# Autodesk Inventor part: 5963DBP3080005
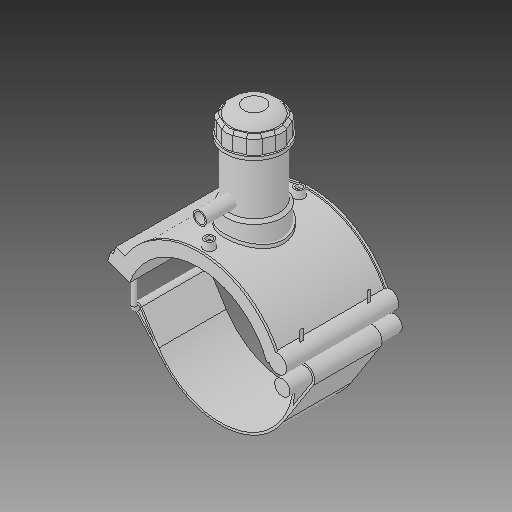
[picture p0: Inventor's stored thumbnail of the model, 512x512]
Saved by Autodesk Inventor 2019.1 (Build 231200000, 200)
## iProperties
Created: 2017-07
Part Number: 5963DBP3080005
Material: Generic
Description: PLASSON TAPPING SADDLE 8''DIPS x 1/2''IPS
Document SubType Name: Modeling
Designer: KIM
Density: 1 g/cm^3
Appearance: Default
Author: KIM
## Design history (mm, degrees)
derived "5963DBP_5963BUP.ipt"
feature "Solid1::5963DBP_5963BUP.ipt"
feature "Solid2::5963DBP_5963BUP.ipt"
feature "Solid3::5963DBP_5963BUP.ipt"
tag "TaggingFeature1"
body "Solid1"
body "Solid2"
body "Solid3"
other parameters: "d0" = 228.9, "d2" = 269.748, "d3" = 57.225, "d4" = 176.022, "d5" = 0, "d6" = 0.1, "d8" = 0, "d19" = 6, "d20" = 6, "d21" = 105.6132, "d23" = 0, "d24" = 52.8066, "d26" = 0, "d27" = 3, "d28" = 3, "d29" = 3, "d30" = 76.3, "d31" = 6, "d32" = 0, "d33" = 0, "d34" = 0.6, "d40" = 138.07248, "d41" = 91.56, "d43" = 0, "d45" = 0, "d47" = 238.3752, "d70" = 15, "d72" = 0, "d73" = 6, "d75" = 5, "d76" = 0, "d77" = 11.445, "d78" = 144.45, "d79" = 15, "d80" = 70.4088, "d82" = 5 deg, "d84" = 4, "d85" = 14, "d86" = 0, "d87" = 3, "d88" = 0, "d89" = 1, "d90" = 1, "d91" = 140.8176, "d92" = 0, "d93" = 0.5, "d94" = 120.47368, "d96" = 270.83448, "d97" = 3.52044, "d98" = 0, "d120" = 140 deg, "d121" = 24.228, "d122" = 20 deg, "d123" = 531.048, "d124" = 159.3144, "d126" = 0, "d143" = 235.767, "d145" = 28.17231, "d149" = 3.4335, "d150" = 30.98954, "d153" = 176.022, "d154" = 0, "d156" = 132.762, "d157" = 160 deg, "d159" = 7.3248, "d161" = 3.4335, "d162" = 105.6132, "d163" = 0, "d164" = 114.45, "d167" = 22.89, "d168" = 129.5239, "d170" = 3.4335, "d172" = 0, "d173" = 1, "d175" = 114.45, "d176" = 20 deg, "d177" = 16.023, "d178" = 36.624, "d180" = 0, "d183" = 14.6496, "d184" = 12.8184, "d185" = 57.20715, "d186" = 57.20715, "d187" = 132.762, "d188" = 10.9872, "d189" = 16.023, "d190" = 0, "d191" = 199.143, "d193" = 7.3248, "d194" = 6.16077, "d195" = 90 deg, "d197" = 0, "d199" = 0, "d200" = 18.312, "d202" = 0, "d203" = 177.038, "d204" = 86.982, "d205" = 64.092, "d206" = 77.826, "d207" = 132.7785, "d208" = 138.08964, "d209" = 164.64534, "d210" = 78.7416, "d211" = 91.56, "d212" = 73.248, "d213" = 48.9816, "d216" = 0, "d217" = 22.89, "d218" = 22.89, "d219" = 4.578, "d222" = 228.9, "d224" = 0, "d225" = 65.024, "d226" = 21.2, "d227" = 16.96, "d228" = 85.09, "d230" = 4.578, "d_" = 228.9, "B_" = 179.832, "L_" = 176.022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
